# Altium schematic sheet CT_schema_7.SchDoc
size 278 x 170 mm
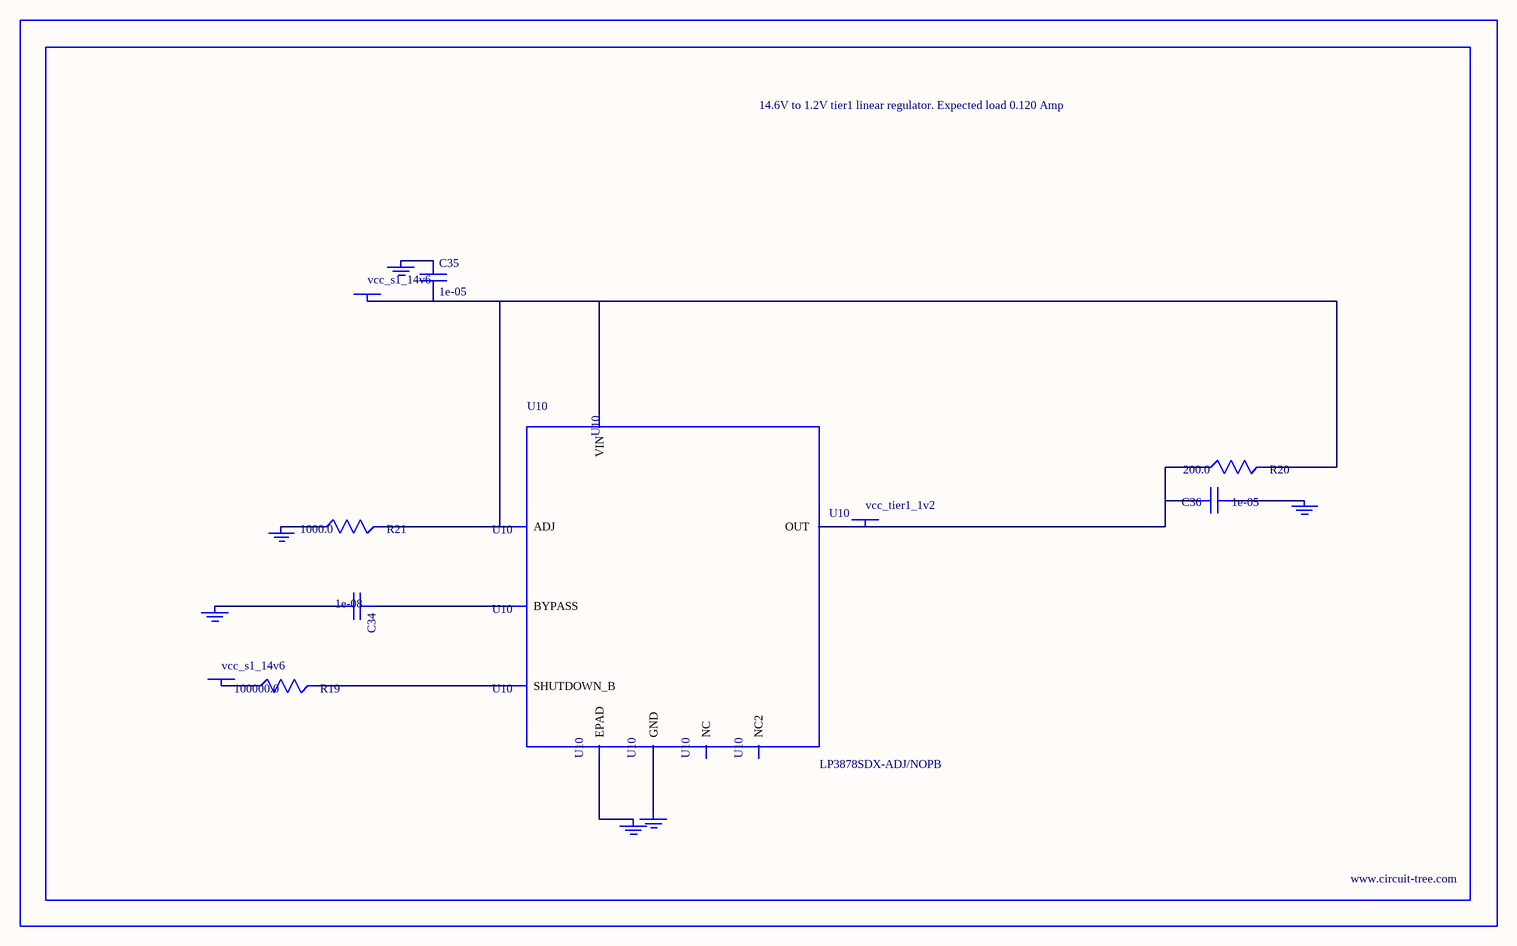
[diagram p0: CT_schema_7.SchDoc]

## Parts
BORDER6  (no value)
C34  1e-08  [C0402]
C35  1e-05  [C1210]
C36  1e-05  [C0805]
GND_INSTANCE_6_0  (no value)
GND_INSTANCE_6_1  (no value)
GND_INSTANCE_6_2  (no value)
GND_INSTANCE_6_3  (no value)
GND_INSTANCE_6_4  (no value)
GND_INSTANCE_6_5  (no value)
POWER_INSTANCE_6_0  vcc_s1_14v6
POWER_INSTANCE_6_1  vcc_s1_14v6
POWER_INSTANCE_6_2  vcc_tier1_1v2
R19  100000.0  [R0603]
R20  200.0  [R0603]
R21  1000.0  [R0603]
U10  LP3878SDX-ADJ/NOPB  [WSON-8]

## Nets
NetC34_1: C34.1 U10.1(BYPASS)
NetC34_2: C34.2 GND_INSTANCE_6_0.0(GND)
NetC35_1: C35.1 GND_INSTANCE_6_1.0(GND)
NetC35_2: C35.2 POWER_INSTANCE_6_0.0(PWR) R20.2 R21.2 U10.4(VIN) U10.6(ADJ)
NetC36_1: C36.1 GND_INSTANCE_6_2.0(GND)
NetC36_2: C36.2 POWER_INSTANCE_6_2.0(PWR) R20.1 U10.5(OUT)
NetGND_INSTANCE_6_3_0: GND_INSTANCE_6_3.0(GND) R21.1
NetGND_INSTANCE_6_4_0: GND_INSTANCE_6_4.0(GND) U10.PAD(EPAD)
NetGND_INSTANCE_6_5_0: GND_INSTANCE_6_5.0(GND) U10.3(GND)
NetPOWER_INSTANCE_6_1_0: POWER_INSTANCE_6_1.0(PWR) R19.1
NetR19_2: R19.2 U10.8(SHUTDOWN_B)

Not connected (* = marked no-connect by the designer): U10 2(NC) 7(NC2)

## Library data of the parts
BORDER6 = BORDER_PAGE6
C34 = C0402C103K3RAC
C35 = C1210C106K5PACTU
C36 = GRM219R60J106ME19D
GND_INSTANCE_6_0-GND_INSTANCE_6_5 = GND
POWER_INSTANCE_6_0-POWER_INSTANCE_6_2 = PWR
R19 = RC0603JR-07100KL
R20 = RC0603JR-07200RL
R21 = RC0603JR-071KL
